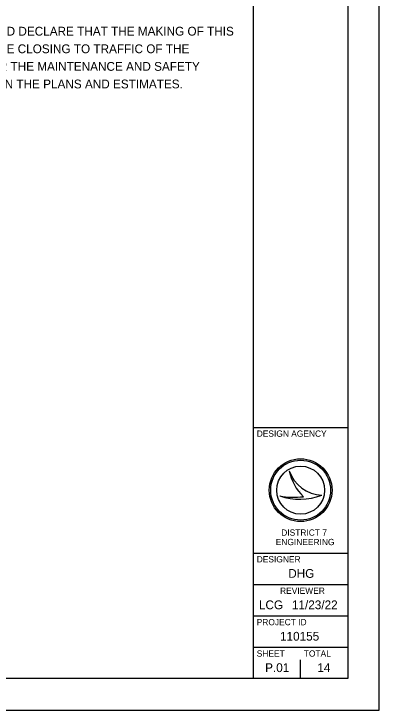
# Model space of a CAD drawing. Extents: x -31.7 to 34, y 0 to 22.
# Drawn here: x 28.18 to 34, y 0 to 11.08 of the extents above; entities that cross this region are included whole.
import ezdxf

# ---------------------------------------------------------------- set-up
doc = ezdxf.new("R2010")
doc.units = 0
for name, color, linetype in [('SH_Border', 7, 'Continuous'), ('SH_Cut_Line', 7, 'Continuous'), ('SH_Data', 7, 'Continuous')]:
    doc.layers.add(name, color=color, linetype=linetype)

msp = doc.modelspace()

# ---------------------------------------------------------------- linework, layer by layer
at = {"layer": 'SH_Border'}
for p, q in [((32, 0.5), (32, 21.5)), ((32, 4.5), (33.5, 4.5)), ((32, 2.5), (33.5, 2.5)), ((32, 2), (33.5, 2)), ((32, 1.5), (33.5, 1.5)), ((32, 1), (33.5, 1))]:
    msp.add_line(p, q, dxfattribs=at)
msp.add_lwpolyline([(1.5, 21.5), (33.5, 21.5), (33.5, 0.5), (1.5, 0.5)], close=True, dxfattribs=at)
at = {"layer": 'SH_Cut_Line'}
msp.add_lwpolyline([(0, 0), (34, 0), (34, 22), (0, 22)], close=True, dxfattribs=at)
at = {"layer": 'SH_Data'}
for p, q in [((32.567, 3.81), (32.567, 3.81)), ((32.75, 3.5), (32.75, 3.5)), ((32.417, 3.41), (32.417, 3.41)), ((33.087, 3.419), (33.087, 3.419)), ((32.75, 0.5), (32.75, 0.8)), ((32.375, 0.675), (32.375, 0.675))]:
    msp.add_line(p, q, dxfattribs=at)
for radius in [0.5, 0.477, 0.477, 0.382]:
    msp.add_circle((32.75, 3.5), radius, dxfattribs=at)
for centre, radius, start, end in [((33.116, 3.998), 0.58, 198.9257, 198.9319), ((33.347, 3.97), 0.796, 191.6379, 191.6421), ((33.116, 3.998), 0.58, 198.9319, 267.1657), ((33.347, 3.97), 0.796, 191.6421, 226.0947), ((32.739, 4.37), 1.013, 251.4576, 290.0832), ((32.648, 4.654), 1.266, 259.4964, 259.4995), ((32.739, 4.37), 1.013, 251.4527, 251.4576), ((32.648, 4.654), 1.266, 259.4995, 276.6672)]:
    msp.add_arc(centre, radius, start, end, dxfattribs=at)

# ---------------------------------------------------------------- texts
for s, height, p in [(' I HEREBY APPROVE THESE PLANS AND DECLARE THAT THE MAKING OF THIS', 0.14, (24.528, 10.735)), ('IMPROVEMENT WILL NOT REQUIRE THE CLOSING TO TRAFFIC OF THE', 0.14, (24.528, 10.455)), ('HIGHWAY AND THAT PROVISIONS FOR THE MAINTENANCE AND SAFETY', 0.14, (24.528, 10.175)), ('OF TRAFFIC WILL BE AS SET FORTH ON THE PLANS AND ESTIMATES.', 0.14, (24.528, 9.895)), ('DESIGN AGENCY', 0.1, (32.05, 4.35)), ('DISTRICT 7', 0.1, (32.441, 2.775)), ('ENGINEERING', 0.1, (32.353, 2.625)), ('DESIGNER', 0.1, (32.05, 2.35)), ('DHG', 0.14, (32.552, 2.105)), ('REVIEWER', 0.1, (32.422, 1.85)), ('LCG', 0.14, (32.085, 1.605)), ('11/23/22', 0.14, (32.611, 1.605)), ('PROJECT ID', 0.1, (32.05, 1.35)), ('110155', 0.14, (32.421, 1.105)), ('SHEET', 0.1, (32.05, 0.85)), ('TOTAL', 0.1, (32.8, 0.85)), ('P.01', 0.14, (32.184, 0.605)), ('14', 0.14, (33.016, 0.605))]:
    msp.add_text(s, height=height, dxfattribs=at).set_placement(p)

doc.saveas('drawing.dxf')
